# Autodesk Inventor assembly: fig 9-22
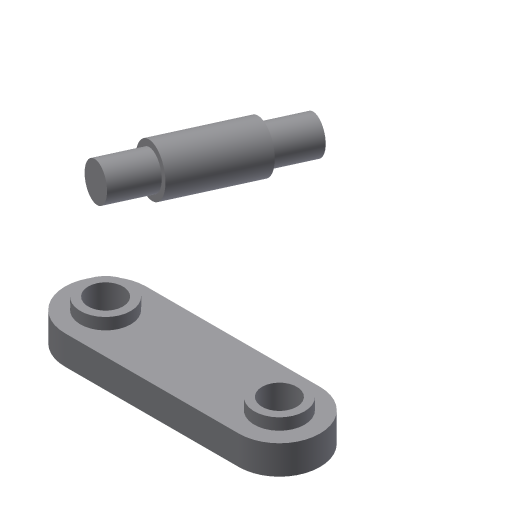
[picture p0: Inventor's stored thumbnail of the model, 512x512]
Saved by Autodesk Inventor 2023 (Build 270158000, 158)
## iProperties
Created: 2002-01
Part Number: fig 9-22
Document SubType Name: Assembly
Designer: ***
Control State: 0
Master: False
Checked Out: False
Shininess: 64.0
Length Units: 11269
Angle Units: 11279
Time Units: 11290
Mass Units: 11283
Length Display Precision: 3
Angle Display Precision: 2
Density: 0.0
Volumn: 0.0
Area: 0.0
PropertySet Name: Model Information
Author: ***
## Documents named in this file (3)
- D:\PROJECTS\Project 2022\Autodesk Inventor For Professional 2023\RESOURCES INVENTOR 2023\RESOURCES INVENTOR 2023\Inventor_2023_Part\Inventor_2023_Part\c09_Inv_2023_prt\fig 9-22.iam
- D:\PROJECTS\Project 2022\Autodesk Inventor For Professional 2023\RESOURCES INVENTOR 2023\RESOURCES INVENTOR 2023\Inventor_2023_Part\Inventor_2023_Part\c09_Inv_2023_prt\Part5.ipt
- D:\PROJECTS\Project 2022\Autodesk Inventor For Professional 2023\RESOURCES INVENTOR 2023\RESOURCES INVENTOR 2023\Inventor_2023_Part\Inventor_2023_Part\c09_Inv_2023_prt\Part6.ipt
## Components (2 placed, 2 different names)
1. Part5:1
2. Part6:1
